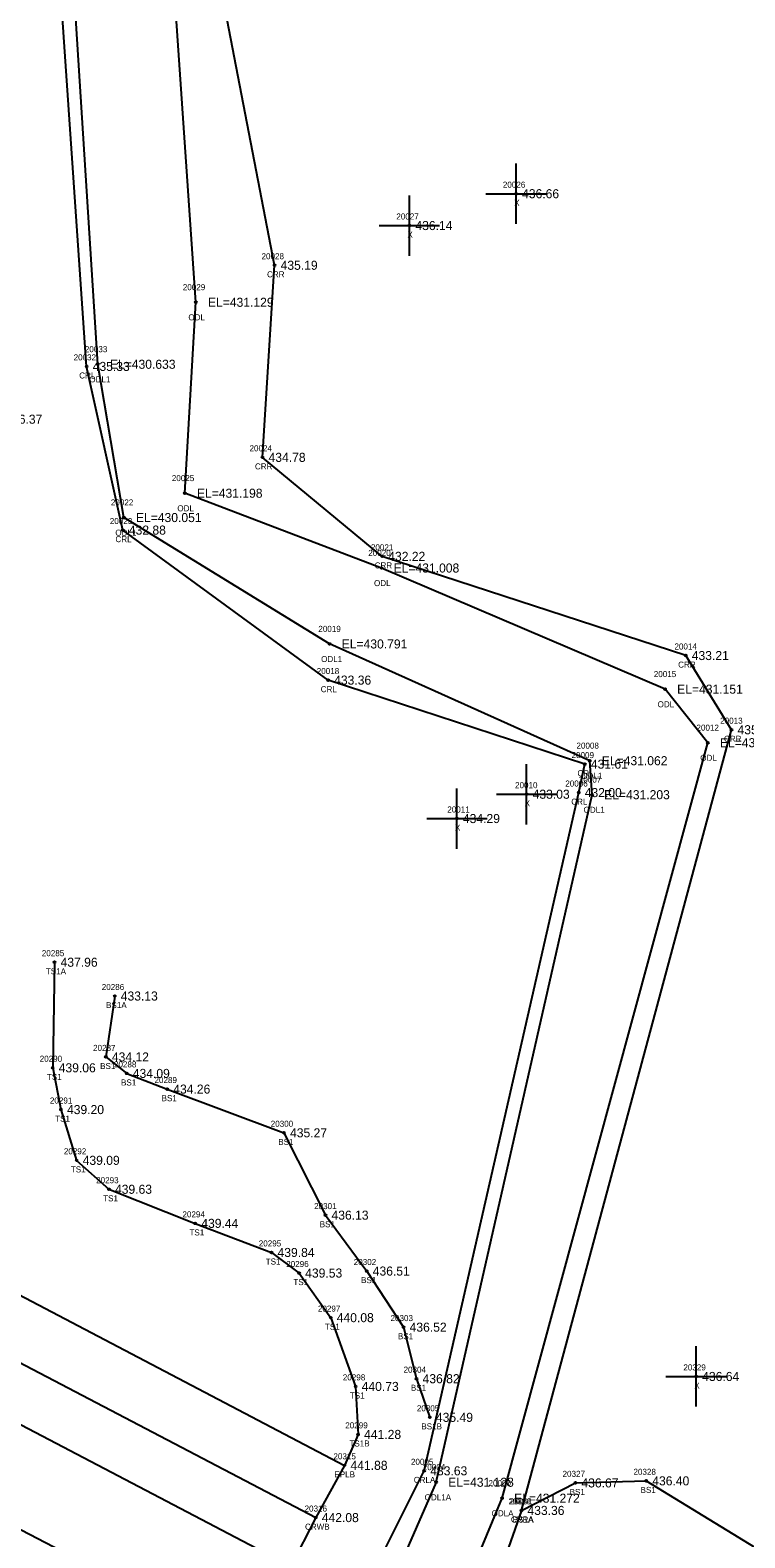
# Model space of a CAD drawing. Extents: x 1810114 to 1811498, y 790790 to 791824.
# Drawn here: x 1810716.3 to 1810834.7, y 791292.3 to 791542.1 of the extents above; entities that cross this region are included whole.
import ezdxf

# ---------------------------------------------------------------- set-up
doc = ezdxf.new("R2010")
doc.units = 0
for name, color, linetype in [('RD_DTM_BkLn1', 7, 'Continuous'), ('RD_DTM_BkLn2', 7, 'Continuous'), ('RD_DTM_BkLn_txCode', 7, 'Continuous'), ('RD_EX_H2O', 7, 'Continuous'), ('RD_EX_H2O_txCode', 7, 'Continuous'), ('RD_EX_Misc', 7, 'Continuous'), ('RD_EX_Misc_txCode', 7, 'Continuous'), ('RD_EX_Road', 7, 'Continuous'), ('RD_EX_Road_txCode', 7, 'Continuous'), ('RD_EX_TX_H2O_ELEV', 7, 'Continuous'), ('RD_EX_TX_Misc_ELEV', 7, 'Continuous'), ('RD_EX_TX_Road_ELEV', 7, 'Continuous'), ('RD_HC_Survey_ELEV', 7, 'Continuous'), ('RD_HC_Survey_txCode', 7, 'Continuous'), ('RD_SMD_Locator', 7, 'Continuous')]:
    doc.layers.add(name, color=color, linetype=linetype)

msp = doc.modelspace()

# ---------------------------------------------------------------- linework, layer by layer
at = {"layer": 'RD_DTM_BkLn1'}
msp.add_lwpolyline([(1810142.92, 791624.85), (1810231.36, 791577.96), (1810319.85, 791530.5), (1810408.61, 791483.38), (1810496.8, 791436.85), (1810585.08, 791388.93), (1810674.47, 791342.37), (1810763.64, 791295.68)], dxfattribs=at)
at = {"layer": 'RD_DTM_BkLn2'}
for points in [[(1810136.46, 791613.23), (1810225.09, 791566.55), (1810313.34, 791519.56), (1810402.58, 791471.61), (1810490.03, 791423.34), (1810516.06, 791407.46), (1810541.24, 791393.02), (1810575.56, 791368.65), (1810662.82, 791320.73), (1810730.85, 791285.33), (1810742.82, 791282.19), (1810752.34, 791280.87), (1810757.12, 791283.77)], [(1810720.37, 791387.68), (1810720.06, 791370.19), (1810721.43, 791363.27), (1810724.03, 791354.86), (1810729.38, 791350.07), (1810743.68, 791344.42), (1810756.31, 791339.6), (1810760.89, 791336.19), (1810766.12, 791328.8), (1810770.25, 791317.41), (1810770.65, 791309.46)], [(1810730.34, 791382.08), (1810728.87, 791371.99), (1810732.33, 791369.26), (1810739.04, 791366.66), (1810758.38, 791359.42), (1810765.25, 791345.78), (1810772.08, 791336.52), (1810778.19, 791327.23), (1810780.34, 791318.69), (1810782.55, 791312.29)], [(1810770.65, 791309.46), (1810768.4, 791304.34), (1810763.64, 791295.68), (1810759.54, 791287.61), (1810757.12, 791283.77)], [(1810797.71, 791296.87), (1810806.65, 791301.43), (1810818.39, 791301.77), (1810860.19, 791276.21), (1810904.39, 791251.18), (1810946.65, 791228.17), (1810992.83, 791210.21), (1811039.32, 791196), (1811086.62, 791185.05), (1811136.39, 791175.32), (1811184.54, 791168.49), (1811233.77, 791164.27), (1811283.33, 791162.64), (1811288.69, 791162.37)]]:
    msp.add_lwpolyline(points, dxfattribs=at)
at = {"layer": 'RD_EX_H2O'}
for p, q in [((1810767.47, 791275.24), (1810781.61, 791303.43)), ((1810783.58, 791301.54), (1810771.9, 791274.91)), ((1810781.26, 791266.77), (1810794.5, 791298.9)), ((1810797.71, 791296.87), (1810787.01, 791266.28))]:
    msp.add_line(p, q, dxfattribs=at)
for points in [[(1810794.5, 791298.9), (1810828.59, 791424.04), (1810821.51, 791432.91), (1810774.54, 791452.98), (1810741.95, 791465.37), (1810743.78, 791497), (1810736.7, 791599.78), (1810749.88, 791692.36), (1810769.68, 791736.66), (1810784.24, 791774.17), (1810766.9, 791808.95)], [(1810797.71, 791296.87), (1810832.51, 791426.19), (1810824.93, 791438.48), (1810774.65, 791454.91), (1810754.82, 791471.31), (1810756.82, 791503.13), (1810738.07, 791600.2), (1810752.73, 791691.4), (1810775.78, 791733), (1810786.04, 791774.85), (1810772.38, 791809.33)], [(1810781.61, 791303.43), (1810807.2, 791415.78), (1810808.22, 791420.49), (1810765.69, 791434.41), (1810731.68, 791459.26), (1810725.69, 791486.37), (1810718.09, 791596.36), (1810712.45, 791605.3), (1810726.19, 791694.57), (1810745.89, 791743.36), (1810754.16, 791771.51), (1810757.05, 791789.67), (1810743.21, 791805.43)], [(1810783.58, 791301.54), (1810809.42, 791415.43), (1810809.03, 791421.06), (1810765.94, 791440.4), (1810731.85, 791461.34), (1810727.54, 791486.73), (1810720.53, 791597.07), (1810716.45, 791606.79), (1810735.63, 791693.4), (1810750.76, 791743.08), (1810758.52, 791771.58), (1810758.6, 791790.56), (1810750.48, 791805.79)]]:
    msp.add_lwpolyline(points, dxfattribs=at)
at = {"layer": 'RD_EX_Misc'}
for p, q in [((1810796.82, 791509.98), (1810796.82, 791519.98)), ((1810791.82, 791514.98), (1810801.82, 791514.98)), ((1810779.15, 791504.71), (1810779.15, 791514.71)), ((1810774.15, 791509.71), (1810784.15, 791509.71)), ((1810798.57, 791410.51), (1810798.57, 791420.51)), ((1810787.02, 791406.48), (1810787.02, 791416.48)), ((1810793.57, 791415.51), (1810803.57, 791415.51)), ((1810782.02, 791411.48), (1810792.02, 791411.48)), ((1810826.66, 791314.06), (1810826.66, 791324.06)), ((1810821.66, 791319.06), (1810831.66, 791319.06))]:
    msp.add_line(p, q, dxfattribs=at)
at = {"layer": 'RD_EX_Road'}
for points in [[(1810147.3, 791633.32), (1810235.73, 791586.37), (1810316.89, 791542.45), (1810324.32, 791538.42), (1810350.04, 791524.6), (1810412.94, 791490.75), (1810461.45, 791466.07), (1810501.18, 791444.55), (1810589.18, 791397.37), (1810679.08, 791351.18), (1810768.4, 791304.34)], [(1810138.18, 791616.8), (1810226.92, 791569.59), (1810315.11, 791521.87), (1810404.37, 791475.11), (1810492.73, 791428.56), (1810580.86, 791380.55), (1810670.21, 791334.43), (1810759.54, 791287.61)]]:
    msp.add_lwpolyline(points, dxfattribs=at)
at = {"layer": 'RD_SMD_Locator'}
for centre in [(1810796.82, 791514.98), (1810779.15, 791509.71), (1810756.82, 791503.13), (1810743.78, 791497), (1810725.69, 791486.37), (1810727.54, 791486.73), (1810754.82, 791471.31), (1810741.95, 791465.37), (1810731.85, 791461.34), (1810731.68, 791459.26), (1810774.65, 791454.91), (1810774.54, 791452.98), (1810765.94, 791440.4), (1810824.93, 791438.48), (1810765.69, 791434.41), (1810821.51, 791432.91), (1810832.51, 791426.19), (1810828.59, 791424.04), (1810808.22, 791420.49), (1810809.03, 791421.06), (1810798.57, 791415.51), (1810807.2, 791415.78), (1810809.42, 791415.43), (1810787.02, 791411.48), (1810720.37, 791387.68), (1810730.34, 791382.08), (1810720.06, 791370.19), (1810728.87, 791371.99), (1810732.33, 791369.26), (1810739.04, 791366.66), (1810721.43, 791363.27), (1810758.38, 791359.42), (1810724.03, 791354.86), (1810729.38, 791350.07), (1810765.25, 791345.78), (1810743.68, 791344.42), (1810756.31, 791339.6), (1810760.89, 791336.19), (1810772.08, 791336.52), (1810766.12, 791328.8), (1810778.19, 791327.23), (1810770.25, 791317.41), (1810780.34, 791318.69), (1810826.66, 791319.06), (1810782.55, 791312.29), (1810770.65, 791309.46), (1810768.4, 791304.34), (1810781.61, 791303.43), (1810783.58, 791301.54), (1810806.65, 791301.43), (1810818.39, 791301.77), (1810794.5, 791298.9), (1810763.64, 791295.68), (1810797.71, 791296.87), (1810797.71, 791296.87)]:
    msp.add_circle(centre, 0.15, dxfattribs=at)

# ---------------------------------------------------------------- texts
at = {"layer": 'RD_DTM_BkLn_txCode'}
for s, p in [('20285', (1810718.26, 791388.68)), ('TS1A', (1810718.93, 791385.68)), ('20286', (1810728.19, 791383.08)), ('BS1A', (1810728.9, 791380.08)), ('20287', (1810726.75, 791372.99)), ('20290', (1810717.91, 791371.19)), ('BS1', (1810727.92, 791369.99)), ('20288', (1810730.21, 791370.26)), ('TS1', (1810719.1, 791368.19)), ('BS1', (1810731.38, 791367.26)), ('20289', (1810736.93, 791367.66)), ('20291', (1810719.6, 791364.27)), ('BS1', (1810738.1, 791364.66)), ('TS1', (1810720.47, 791361.27)), ('20300', (1810756.18, 791360.42)), ('BS1', (1810757.43, 791357.42)), ('20292', (1810721.91, 791355.86)), ('TS1', (1810723.07, 791352.86)), ('20293', (1810727.26, 791351.07)), ('TS1', (1810728.42, 791348.07)), ('20301', (1810763.37, 791346.78)), ('20294', (1810741.56, 791345.42)), ('TS1', (1810742.72, 791342.42)), ('BS1', (1810764.3, 791343.78)), ('20295', (1810754.2, 791340.6)), ('TS1', (1810755.35, 791337.6)), ('20296', (1810758.75, 791337.19)), ('20302', (1810769.93, 791337.52)), ('TS1', (1810759.93, 791334.19)), ('BS1', (1810771.14, 791334.52)), ('20297', (1810764, 791329.8)), ('TS1', (1810765.16, 791326.8)), ('20303', (1810776.03, 791328.23)), ('BS1', (1810777.25, 791325.23)), ('20304', (1810778.19, 791319.69)), ('20298', (1810768.13, 791318.41)), ('BS1', (1810779.4, 791316.69)), ('TS1', (1810769.29, 791315.41)), ('20305', (1810780.39, 791313.29)), ('20299', (1810768.53, 791310.46)), ('BS1B', (1810781.13, 791310.29)), ('TS1B', (1810769.22, 791307.46)), ('20327', (1810804.53, 791302.43)), ('20328', (1810816.27, 791302.77)), ('BS1', (1810805.7, 791299.43)), ('BS1', (1810817.45, 791299.77)), ('20326', (1810795.56, 791297.87)), ('BS1A', (1810796.27, 791294.87))]:
    msp.add_text(s, height=1, dxfattribs=at).set_placement(p)
at = {"layer": 'RD_EX_H2O_txCode'}
for s, p in [('20028', (1810754.66, 791504.13)), ('20029', (1810741.62, 791499)), ('CRR', (1810755.57, 791501.13)), ('ODL', (1810742.54, 791494)), ('20032', (1810723.53, 791487.37)), ('20033', (1810725.39, 791488.73)), ('CRL', (1810724.46, 791484.37)), ('ODL1', (1810726.13, 791483.73)), ('20024', (1810752.67, 791472.31)), ('CRR', (1810753.57, 791469.31)), ('20025', (1810739.8, 791467.37)), ('20022', (1810729.7, 791463.34)), ('ODL', (1810740.71, 791462.37)), ('20023', (1810729.53, 791460.26)), ('ODL1', (1810730.44, 791458.34)), ('CRL', (1810730.46, 791457.26)), ('20020', (1810772.34, 791454.98)), ('20021', (1810772.78, 791455.91)), ('CRR', (1810773.4, 791452.91)), ('ODL', (1810773.29, 791449.98)), ('20019', (1810764.07, 791442.4)), ('20014', (1810823.06, 791439.48)), ('ODL1', (1810764.53, 791437.4)), ('CRR', (1810823.68, 791436.48)), ('20018', (1810763.81, 791435.41)), ('20015', (1810819.64, 791434.91)), ('CRL', (1810764.46, 791432.41)), ('ODL', (1810820.27, 791429.91)), ('20013', (1810830.64, 791427.19)), ('20012', (1810826.71, 791426.04)), ('CRR', (1810831.26, 791424.19)), ('20009', (1810806.02, 791421.49)), ('20008', (1810806.83, 791423.06)), ('ODL', (1810827.34, 791421.04)), ('20006', (1810804.98, 791416.78)), ('CRL', (1810806.99, 791418.49)), ('20007', (1810807.23, 791417.43)), ('ODL1', (1810807.62, 791418.06)), ('CRL', (1810805.97, 791413.78)), ('ODL1', (1810808.01, 791412.43)), ('20005', (1810779.41, 791304.43)), ('20004', (1810781.38, 791303.54)), ('CRLA', (1810779.89, 791301.43)), ('20000', (1810792.26, 791300.9)), ('ODL1A', (1810781.68, 791298.54)), ('20001', (1810795.79, 791297.87)), ('ODLA', (1810792.77, 791295.9)), ('CRRA', (1810795.97, 791294.87))]:
    msp.add_text(s, height=1, dxfattribs=at).set_placement(p)
at = {"layer": 'RD_EX_Misc_txCode'}
for s, p in [('20026', (1810794.64, 791515.98)), ('X', (1810796.51, 791512.98)), ('20027', (1810776.99, 791510.71)), ('X', (1810778.83, 791507.71)), ('20010', (1810796.66, 791416.51)), ('20011', (1810785.43, 791412.48)), ('X', (1810798.25, 791413.51)), ('X', (1810786.7, 791409.48)), ('20329', (1810824.54, 791320.06)), ('X', (1810826.35, 791317.06))]:
    msp.add_text(s, height=1, dxfattribs=at).set_placement(p)
at = {"layer": 'RD_EX_Road_txCode'}
for s, p in [('20315', (1810766.57, 791305.34)), ('EPLB', (1810766.73, 791302.34))]:
    msp.add_text(s, height=1, dxfattribs=at).set_placement(p)
at = {"layer": 'RD_EX_TX_H2O_ELEV'}
for s, p in [('435.19', (1810757.82, 791502.38)), ('EL=431.129', (1810745.78, 791496.25)), ('EL=430.633', (1810729.54, 791485.98)), ('435.33', (1810726.69, 791485.62)), ('434.78', (1810755.82, 791470.56)), ('EL=431.198', (1810743.95, 791464.62)), ('432.88', (1810732.68, 791458.51)), ('EL=430.051', (1810733.85, 791460.59)), ('432.22', (1810775.65, 791454.16)), ('EL=431.008', (1810776.54, 791452.23)), ('EL=430.791', (1810767.94, 791439.65)), ('433.21', (1810825.93, 791437.73)), ('433.36', (1810766.69, 791433.66)), ('EL=431.151', (1810823.51, 791432.16)), ('435.51', (1810833.51, 791425.44)), ('EL=430.841', (1810830.59, 791423.29)), ('431.61', (1810809.22, 791419.74)), ('EL=431.062', (1810811.03, 791420.31)), ('432.00', (1810808.2, 791415.03)), ('EL=431.203', (1810811.42, 791414.68)), ('433.63', (1810782.61, 791302.68)), ('EL=431.128', (1810785.58, 791300.79)), ('EL=431.272', (1810796.5, 791298.15)), ('433.36', (1810798.71, 791296.12))]:
    msp.add_text(s, height=1.5, dxfattribs=at).set_placement(p)
at = {"layer": 'RD_EX_TX_Misc_ELEV'}
for s, p in [('436.66', (1810797.82, 791514.23)), ('436.14', (1810780.15, 791508.96)), ('436.37', (1810712.21, 791476.88)), ('433.03', (1810799.57, 791414.76)), ('434.29', (1810788.02, 791410.73)), ('437.96', (1810721.37, 791386.93)), ('433.13', (1810731.34, 791381.33)), ('434.12', (1810729.87, 791371.24)), ('439.06', (1810721.06, 791369.44)), ('434.09', (1810733.33, 791368.51)), ('434.26', (1810740.04, 791365.91)), ('439.20', (1810722.43, 791362.52)), ('435.27', (1810759.38, 791358.67)), ('439.09', (1810725.03, 791354.11)), ('439.63', (1810730.38, 791349.32)), ('439.44', (1810744.68, 791343.67)), ('436.13', (1810766.25, 791345.03)), ('439.84', (1810757.31, 791338.85)), ('439.53', (1810761.89, 791335.44)), ('436.51', (1810773.08, 791335.77)), ('440.08', (1810767.12, 791328.05)), ('436.52', (1810779.19, 791326.48)), ('440.73', (1810771.25, 791316.66)), ('436.82', (1810781.34, 791317.94)), ('436.64', (1810827.66, 791318.31)), ('435.49', (1810783.55, 791311.54)), ('441.28', (1810771.65, 791308.71)), ('436.40', (1810819.39, 791301.02)), ('436.67', (1810807.65, 791300.68)), ('433.36', (1810798.71, 791296.12))]:
    msp.add_text(s, height=1.5, dxfattribs=at).set_placement(p)
at = {"layer": 'RD_EX_TX_Road_ELEV'}
msp.add_text('441.88', height=1.5, dxfattribs=at).set_placement((1810769.4, 791303.59))
at = {"layer": 'RD_HC_Survey_ELEV'}
msp.add_text('442.08', height=1.5, dxfattribs=at).set_placement((1810764.64, 791294.93))
at = {"layer": 'RD_HC_Survey_txCode'}
for s, p in [('20316', (1810761.79, 791296.68)), ('CRWB', (1810761.86, 791293.68))]:
    msp.add_text(s, height=1, dxfattribs=at).set_placement(p)

doc.saveas('drawing.dxf')
